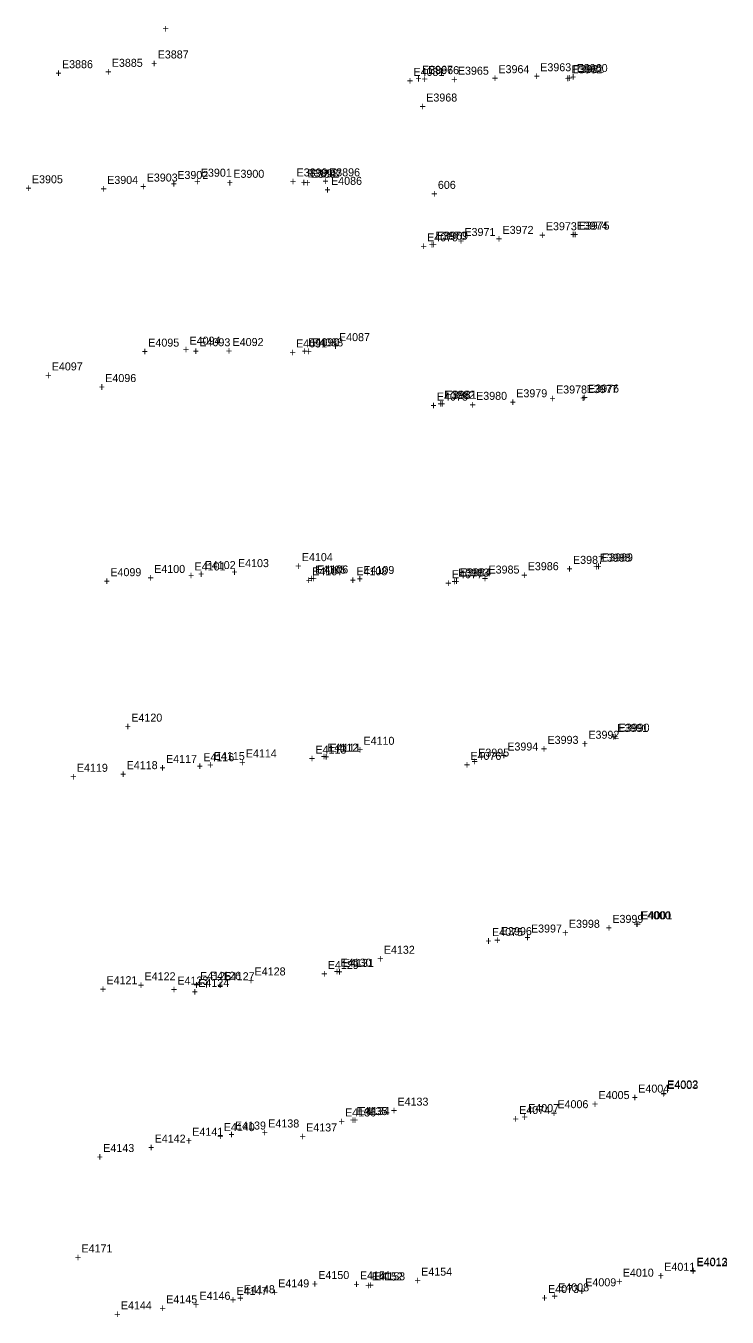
# Model space of a CAD drawing. Extents: x 1667192 to 1669644, y 336680 to 339991.
# Drawn here: x 1667192.3 to 1667411.3, y 337103.7 to 337507.2 of the extents above; entities that cross this region are included whole.
import ezdxf

# ---------------------------------------------------------------- set-up
doc = ezdxf.new("R2010")
doc.units = 0
for name, color, linetype in [('S_Control_Temp_Traverse', 7, 'Continuous'), ('S_Curb_Type_3', 7, 'Continuous'), ('S_Curb_Type_5', 7, 'Continuous'), ('S_Drainage_CB', 7, 'Continuous'), ('S_Ground_Elevation', 7, 'Continuous'), ('S_Guardrail_Beam', 7, 'Continuous'), ('S_Property_IronPipeFound', 7, 'Continuous'), ('S_Roadway_Edge_Pavement', 7, 'Continuous'), ('S_Roadway_Edge_TW', 7, 'Continuous'), ('S_Traffic_Sign_DoublePost', 7, 'Continuous'), ('S_Traffic_Sign_SinglePost', 7, 'Continuous'), ('S_Utilities_GuyWire3', 7, 'Continuous'), ('S_Utilities_Pole_Power', 7, 'Continuous')]:
    doc.layers.add(name, color=color, linetype=linetype)

msp = doc.modelspace()

# ---------------------------------------------------------------- texts
at = {"layer": 'S_Control_Temp_Traverse'}
for s, p in [('606', (1667320.93, 337456.23)), ('606', (1667320.93, 337456.23)), ('606', (1667320.93, 337456.23)), ('606', (1667320.93, 337456.23)), ('+', (1667318.87, 337453.48)), ('+', (1667318.87, 337453.48)), ('+', (1667318.87, 337453.48)), ('+', (1667318.87, 337453.48))]:
    msp.add_text(s, height=2.5, dxfattribs=at).set_placement(p)
at = {"layer": 'S_Curb_Type_3'}
for s, p in [('E3960', (1667364.26, 337492.73)), ('+', (1667362.2, 337489.98))]:
    msp.add_text(s, height=2.5, dxfattribs=at).set_placement(p)
at = {"layer": 'S_Curb_Type_5'}
for s, p in [('+', (1667279.19, 337456.95)), ('E3897', (1667281.26, 337459.7)), ('+', (1667279.61, 337404.27)), ('E4088', (1667281.67, 337407.02)), ('E4106', (1667283.26, 337336.1)), ('+', (1667281.19, 337333.35)), ('E4111', (1667287.12, 337280.36)), ('+', (1667285.06, 337277.61)), ('+', (1667289.22, 337210.41)), ('E4131', (1667291.28, 337213.16)), ('E4134', (1667296.16, 337166.87)), ('+', (1667294.1, 337164.12)), ('E4153', (1667301.02, 337115.26)), ('+', (1667298.96, 337112.51))]:
    msp.add_text(s, height=2.5, dxfattribs=at).set_placement(p)
at = {"layer": 'S_Drainage_CB'}
for s, p in [('E4107', (1667281.7, 337335.5)), ('E4108', (1667295.47, 337335.52)), ('+', (1667279.64, 337332.75)), ('+', (1667293.41, 337332.77))]:
    msp.add_text(s, height=2.5, dxfattribs=at).set_placement(p)
at = {"layer": 'S_Ground_Elevation'}
for s, p in [('+', (1667311.24, 337488.78)), ('E4081', (1667313.3, 337491.53)), ('E3896', (1667286.95, 337460.16)), ('E3905', (1667194.17, 337457.98)), ('E3904', (1667217.66, 337457.78)), ('E3903', (1667230.01, 337458.52)), ('+', (1667237.5, 337456.58)), ('E3902', (1667239.56, 337459.33)), ('+', (1667284.88, 337457.41)), ('E4086', (1667287.57, 337457.49)), ('+', (1667192.11, 337455.23)), ('+', (1667215.6, 337455.03)), ('+', (1667227.95, 337455.77)), ('+', (1667285.5, 337454.74)), ('E4079', (1667317.56, 337439.84)), ('+', (1667315.5, 337437.09)), ('E4094', (1667243.39, 337407.56)), ('E4087', (1667290.05, 337408.66)), ('+', (1667228.44, 337404.2)), ('E4095', (1667230.5, 337406.95)), ('+', (1667241.33, 337404.81)), ('+', (1667287.99, 337405.91)), ('E4097', (1667200.36, 337399.52)), ('+', (1667198.3, 337396.77)), ('E4096', (1667217.07, 337395.88)), ('+', (1667215.01, 337393.13)), ('E4078', (1667320.63, 337390.09)), ('+', (1667318.57, 337387.34)), ('E4099', (1667218.66, 337335.23)), ('E4100', (1667232.34, 337336.24)), ('E4101', (1667244.96, 337337.02)), ('E4109', (1667297.65, 337335.92)), ('+', (1667216.6, 337332.48)), ('+', (1667230.28, 337333.49)), ('+', (1667242.9, 337334.27)), ('+', (1667295.59, 337333.17)), ('+', (1667323.24, 337331.83)), ('E4077', (1667325.3, 337334.58)), ('E4110', (1667297.69, 337282.55)), ('+', (1667295.63, 337279.8)), ('E4118', (1667223.75, 337274.94)), ('E4117', (1667236.04, 337276.88)), ('+', (1667245.61, 337274.67)), ('E4116', (1667247.68, 337277.42)), ('+', (1667329.02, 337275.09)), ('E4076', (1667331.08, 337277.84)), ('+', (1667206.14, 337271.37)), ('E4119', (1667208.2, 337274.12)), ('+', (1667221.69, 337272.19)), ('+', (1667233.98, 337274.13)), ('E4075', (1667337.82, 337222.8)), ('+', (1667335.76, 337220.05)), ('+', (1667301.99, 337214.51)), ('E4132', (1667304.05, 337217.26)), ('E4121', (1667217.44, 337207.76)), ('+', (1667227.28, 337206.23)), ('E4122', (1667229.34, 337208.98)), ('E4123', (1667239.59, 337207.65)), ('E4124', (1667246.11, 337206.91)), ('+', (1667215.38, 337205.01)), ('+', (1667237.53, 337204.9)), ('+', (1667244.05, 337204.16)), ('E4133', (1667308.3, 337169.82)), ('+', (1667306.24, 337167.07)), ('E4074', (1667346.32, 337167.21)), ('E4140', (1667254.07, 337161.85)), ('+', (1667344.25, 337164.46)), ('E4142', (1667232.49, 337158.27)), ('E4141', (1667244.24, 337160.4)), ('+', (1667252.01, 337159.1)), ('E4143', (1667216.45, 337155.34)), ('+', (1667230.43, 337155.52)), ('+', (1667242.18, 337157.65)), ('+', (1667214.39, 337152.59)), ('+', (1667313.64, 337113.95)), ('E4154', (1667315.7, 337116.7)), ('E4146', (1667246.49, 337109.17)), ('E4147', (1667258.05, 337110.7)), ('E4073', (1667355.32, 337111.29)), ('E4144', (1667221.93, 337106.17)), ('+', (1667234.04, 337105.3)), ('E4145', (1667236.1, 337108.05)), ('+', (1667244.43, 337106.42)), ('+', (1667255.99, 337107.95)), ('+', (1667353.25, 337108.54)), ('+', (1667219.87, 337103.42))]:
    msp.add_text(s, height=2.5, dxfattribs=at).set_placement(p)
at = {"layer": 'S_Guardrail_Beam'}
for s, p in [('E3966', (1667317.87, 337492.08)), ('E3961', (1667363.07, 337492.41)), ('+', (1667315.81, 337489.33)), ('+', (1667361.01, 337489.66)), ('E3970', (1667320.17, 337440.34)), ('+', (1667362.82, 337440.75)), ('E3975', (1667364.88, 337443.5)), ('+', (1667318.11, 337437.59)), ('E3976', (1667367.82, 337392.61)), ('+', (1667320.8, 337387.89)), ('E3982', (1667322.86, 337390.64)), ('+', (1667365.76, 337389.86)), ('E3989', (1667372.15, 337339.85)), ('E3983', (1667327.26, 337335.12)), ('+', (1667370.09, 337337.1)), ('+', (1667325.2, 337332.37)), ('E3990', (1667377.36, 337286.66)), ('+', (1667375.3, 337283.91)), ('E4001', (1667384.39, 337228.06)), ('+', (1667382.33, 337225.31)), ('E4002', (1667392.55, 337175.22)), ('+', (1667390.49, 337172.47)), ('E4007', (1667349.1, 337167.81)), ('+', (1667347.04, 337165.06)), ('E4013', (1667401.73, 337119.82)), ('+', (1667399.67, 337117.07))]:
    msp.add_text(s, height=2.5, dxfattribs=at).set_placement(p)
at = {"layer": 'S_Property_IronPipeFound'}
for s, p in [('E4171', (1667209.63, 337123.95)), ('+', (1667207.57, 337121.2))]:
    msp.add_text(s, height=2.5, dxfattribs=at).set_placement(p)
at = {"layer": 'S_Roadway_Edge_Pavement'}
for s, p in [('E3967', (1667315.96, 337492.2)), ('E3962', (1667362.59, 337492.31)), ('+', (1667313.9, 337489.45)), ('+', (1667360.53, 337489.56)), ('+', (1667315.23, 337480.77)), ('E3968', (1667317.29, 337483.52)), ('E3901', (1667246.91, 337460.03)), ('E3898', (1667280.17, 337459.81)), ('+', (1667244.85, 337457.28)), ('+', (1667278.11, 337457.06)), ('E3969', (1667320.68, 337440.36)), ('+', (1667362.2, 337440.75)), ('E3974', (1667364.26, 337443.5)), ('+', (1667318.62, 337437.61)), ('+', (1667244.39, 337404.31)), ('E4093', (1667246.46, 337407.06)), ('+', (1667278.39, 337404.32)), ('E4090', (1667280.45, 337407.07)), ('E3977', (1667367.37, 337392.43)), ('+', (1667321.28, 337387.89)), ('E3981', (1667323.34, 337390.64)), ('+', (1667365.31, 337389.68)), ('E3988', (1667371.5, 337339.74)), ('E4102', (1667248.11, 337337.45)), ('E4105', (1667282.61, 337336.03)), ('E3984', (1667327.81, 337335.17)), ('+', (1667369.44, 337336.99)), ('+', (1667246.05, 337334.7)), ('+', (1667280.55, 337333.28)), ('+', (1667325.75, 337332.42)), ('E3991', (1667376.89, 337286.57)), ('+', (1667374.83, 337283.82)), ('E4112', (1667286.42, 337280.43)), ('E3995', (1667333.52, 337278.86)), ('+', (1667248.89, 337275.04)), ('E4115', (1667250.95, 337277.79)), ('+', (1667284.36, 337277.68)), ('+', (1667331.46, 337276.11)), ('E4000', (1667384.06, 337228.04)), ('E3996', (1667340.6, 337223.08)), ('+', (1667382, 337225.29)), ('+', (1667338.54, 337220.33)), ('+', (1667288.48, 337210.5)), ('E4130', (1667290.54, 337213.25)), ('+', (1667251.97, 337206.25)), ('E4127', (1667254.03, 337209)), ('E4003', (1667392.52, 337175.03)), ('+', (1667390.46, 337172.28)), ('E4135', (1667295.53, 337166.86)), ('E4139', (1667257.57, 337162.36)), ('+', (1667293.47, 337164.11)), ('+', (1667255.51, 337159.61)), ('E4012', (1667401.66, 337119.64)), ('E4152', (1667300.3, 337115.2)), ('+', (1667399.6, 337116.89)), ('E4148', (1667260.35, 337111.22)), ('+', (1667298.23, 337112.45)), ('E4008', (1667358.48, 337111.82)), ('+', (1667258.29, 337108.47)), ('+', (1667356.42, 337109.07))]:
    msp.add_text(s, height=2.5, dxfattribs=at).set_placement(p)
at = {"layer": 'S_Roadway_Edge_TW'}
for s, p in [('E3964', (1667339.83, 337492.38)), ('E3963', (1667352.89, 337492.98)), ('+', (1667325.1, 337489.15)), ('E3965', (1667327.16, 337491.9)), ('+', (1667337.77, 337489.63)), ('+', (1667350.83, 337490.23)), ('E3899', (1667276.8, 337460.12)), ('+', (1667254.99, 337456.94)), ('E3900', (1667257.05, 337459.69)), ('+', (1667274.74, 337457.37)), ('E3971', (1667329.21, 337441.51)), ('E3972', (1667341.12, 337442.16)), ('+', (1667352.57, 337440.56)), ('E3973', (1667354.64, 337443.31)), ('+', (1667327.15, 337438.76)), ('+', (1667339.06, 337439.41)), ('+', (1667254.76, 337404.38)), ('E4092', (1667256.82, 337407.13)), ('+', (1667274.59, 337403.94)), ('E4091', (1667276.65, 337406.69)), ('E3978', (1667357.82, 337392.31)), ('E3980', (1667332.86, 337390.32)), ('+', (1667343.34, 337388.38)), ('E3979', (1667345.4, 337391.13)), ('+', (1667355.76, 337389.56)), ('+', (1667330.8, 337387.57)), ('E4104', (1667278.44, 337339.93)), ('E3987', (1667363.12, 337339.08)), ('+', (1667256.45, 337335.31)), ('E4103', (1667258.51, 337338.06)), ('+', (1667276.38, 337337.18)), ('E3985', (1667336.73, 337336.05)), ('E3986', (1667348.98, 337337.1)), ('+', (1667361.06, 337336.33)), ('+', (1667334.67, 337333.3)), ('+', (1667346.92, 337334.35)), ('E3993', (1667355.16, 337282.84)), ('E3992', (1667367.92, 337284.44)), ('E4114', (1667260.95, 337278.6)), ('E4113', (1667282.69, 337279.79)), ('E3994', (1667342.6, 337280.76)), ('+', (1667353.1, 337280.09)), ('+', (1667365.85, 337281.69)), ('+', (1667258.89, 337275.85)), ('+', (1667280.63, 337277.04)), ('+', (1667340.54, 337278.01)), ('E3999', (1667375.41, 337226.91)), ('E3997', (1667349.99, 337223.9)), ('+', (1667359.77, 337222.63)), ('E3998', (1667361.83, 337225.38)), ('+', (1667373.35, 337224.16)), ('+', (1667347.93, 337221.15)), ('E4128', (1667263.7, 337210.5)), ('E4129', (1667286.53, 337212.52)), ('+', (1667261.63, 337207.75)), ('+', (1667284.47, 337209.77)), ('E4004', (1667383.5, 337173.89)), ('E4005', (1667371.1, 337171.87)), ('+', (1667381.44, 337171.14)), ('E4136', (1667291.95, 337166.44)), ('+', (1667356.19, 337166.27)), ('E4006', (1667358.25, 337169.02)), ('+', (1667369.04, 337169.12)), ('E4138', (1667267.97, 337163)), ('E4137', (1667279.79, 337161.75)), ('+', (1667289.89, 337163.69)), ('+', (1667265.9, 337160.25)), ('+', (1667277.73, 337159)), ('E4011', (1667391.62, 337118.22)), ('E4149', (1667271.08, 337113.05)), ('E4150', (1667283.59, 337115.65)), ('E4151', (1667296.6, 337115.54)), ('E4009', (1667366.95, 337113.38)), ('+', (1667376.59, 337113.63)), ('E4010', (1667378.65, 337116.38)), ('+', (1667389.56, 337115.47)), ('+', (1667269.02, 337110.3)), ('+', (1667281.53, 337112.9)), ('+', (1667294.54, 337112.79)), ('+', (1667364.89, 337110.63))]:
    msp.add_text(s, height=2.5, dxfattribs=at).set_placement(p)
at = {"layer": 'S_Traffic_Sign_DoublePost'}
for s, p in [('+', (1667244.59, 337206.3)), ('E4125', (1667246.66, 337209.05)), ('+', (1667247.72, 337206.39)), ('E4126', (1667249.78, 337209.14))]:
    msp.add_text(s, height=2.5, dxfattribs=at).set_placement(p)
at = {"layer": 'S_Traffic_Sign_SinglePost'}
msp.add_text('+', height=2.5, dxfattribs=at).set_placement((1667234.95, 337505.07))
at = {"layer": 'S_Utilities_GuyWire3'}
for s, p in [('E3887', (1667233.44, 337496.98)), ('E3886', (1667203.55, 337493.93)), ('+', (1667231.38, 337494.23)), ('+', (1667201.48, 337491.18))]:
    msp.add_text(s, height=2.5, dxfattribs=at).set_placement(p)
at = {"layer": 'S_Utilities_Pole_Power'}
for s, p in [('E3885', (1667219.1, 337494.36)), ('+', (1667217.04, 337491.61)), ('+', (1667223.14, 337287.03)), ('E4120', (1667225.2, 337289.78))]:
    msp.add_text(s, height=2.5, dxfattribs=at).set_placement(p)

doc.saveas('drawing.dxf')
